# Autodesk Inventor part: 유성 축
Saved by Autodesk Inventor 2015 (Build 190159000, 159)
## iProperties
Created: 2026-05
Part Number: 유성 축
Material: 일반
Document SubType Name: Modeling
Designer: 104
Density: 1 g/cm^3
Appearance: 기본값
Author: 104
Author: jhkim
Creation Date: 2026-04-27
Sending System: Autodesk Inventor 2027
Preprocessor: ST-DEVELOPER v20.1
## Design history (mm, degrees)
node "유성 축1"
node "솔리드1"
node "기준1"
